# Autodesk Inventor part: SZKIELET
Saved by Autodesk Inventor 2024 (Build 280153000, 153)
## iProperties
Company: ATC
_SkeletonDoc: Frame Skeleton File
_Version: 15.0.0
Created: 2023-03
Part Number: SZKIELET
Material: Ogólny
Document SubType Name: Modeling
Designer: Andrzej Jaskulski
Density: 1 g/cm^3
Appearance: Domyślna
Checked By: A.J.
Engr Approved By: Andrzej Jaskulski
Mfg Approved By: Andrzej Jaskulski
Authority: A.J.
Author: Andrzej Jaskulski
Title: A.J.: Kurs R2024-MEP
Revision Number: 1/24
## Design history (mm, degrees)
sketch "Szkielet odniesienia"
